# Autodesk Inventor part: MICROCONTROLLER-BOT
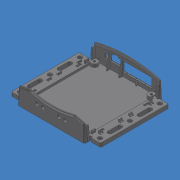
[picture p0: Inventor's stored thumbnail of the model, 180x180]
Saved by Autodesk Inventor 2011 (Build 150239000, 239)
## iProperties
Created: 2007-09
Part Number: MICROCONTROLLER-BOT
Document SubType Name: Modeling
Density: 1 g/cm^3
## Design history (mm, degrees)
feature "Base1"
body "Solid1"
